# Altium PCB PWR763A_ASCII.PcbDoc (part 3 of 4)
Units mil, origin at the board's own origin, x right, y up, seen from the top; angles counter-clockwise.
Board outline 5000 x 7000 mil, 4 copper layers (Top Layer, Signal Layer 1, Signal Layer 2, Bottom Layer), stack 61.2 mil thick; 559 components, 281 nets, 1477 pads, 685 vias.
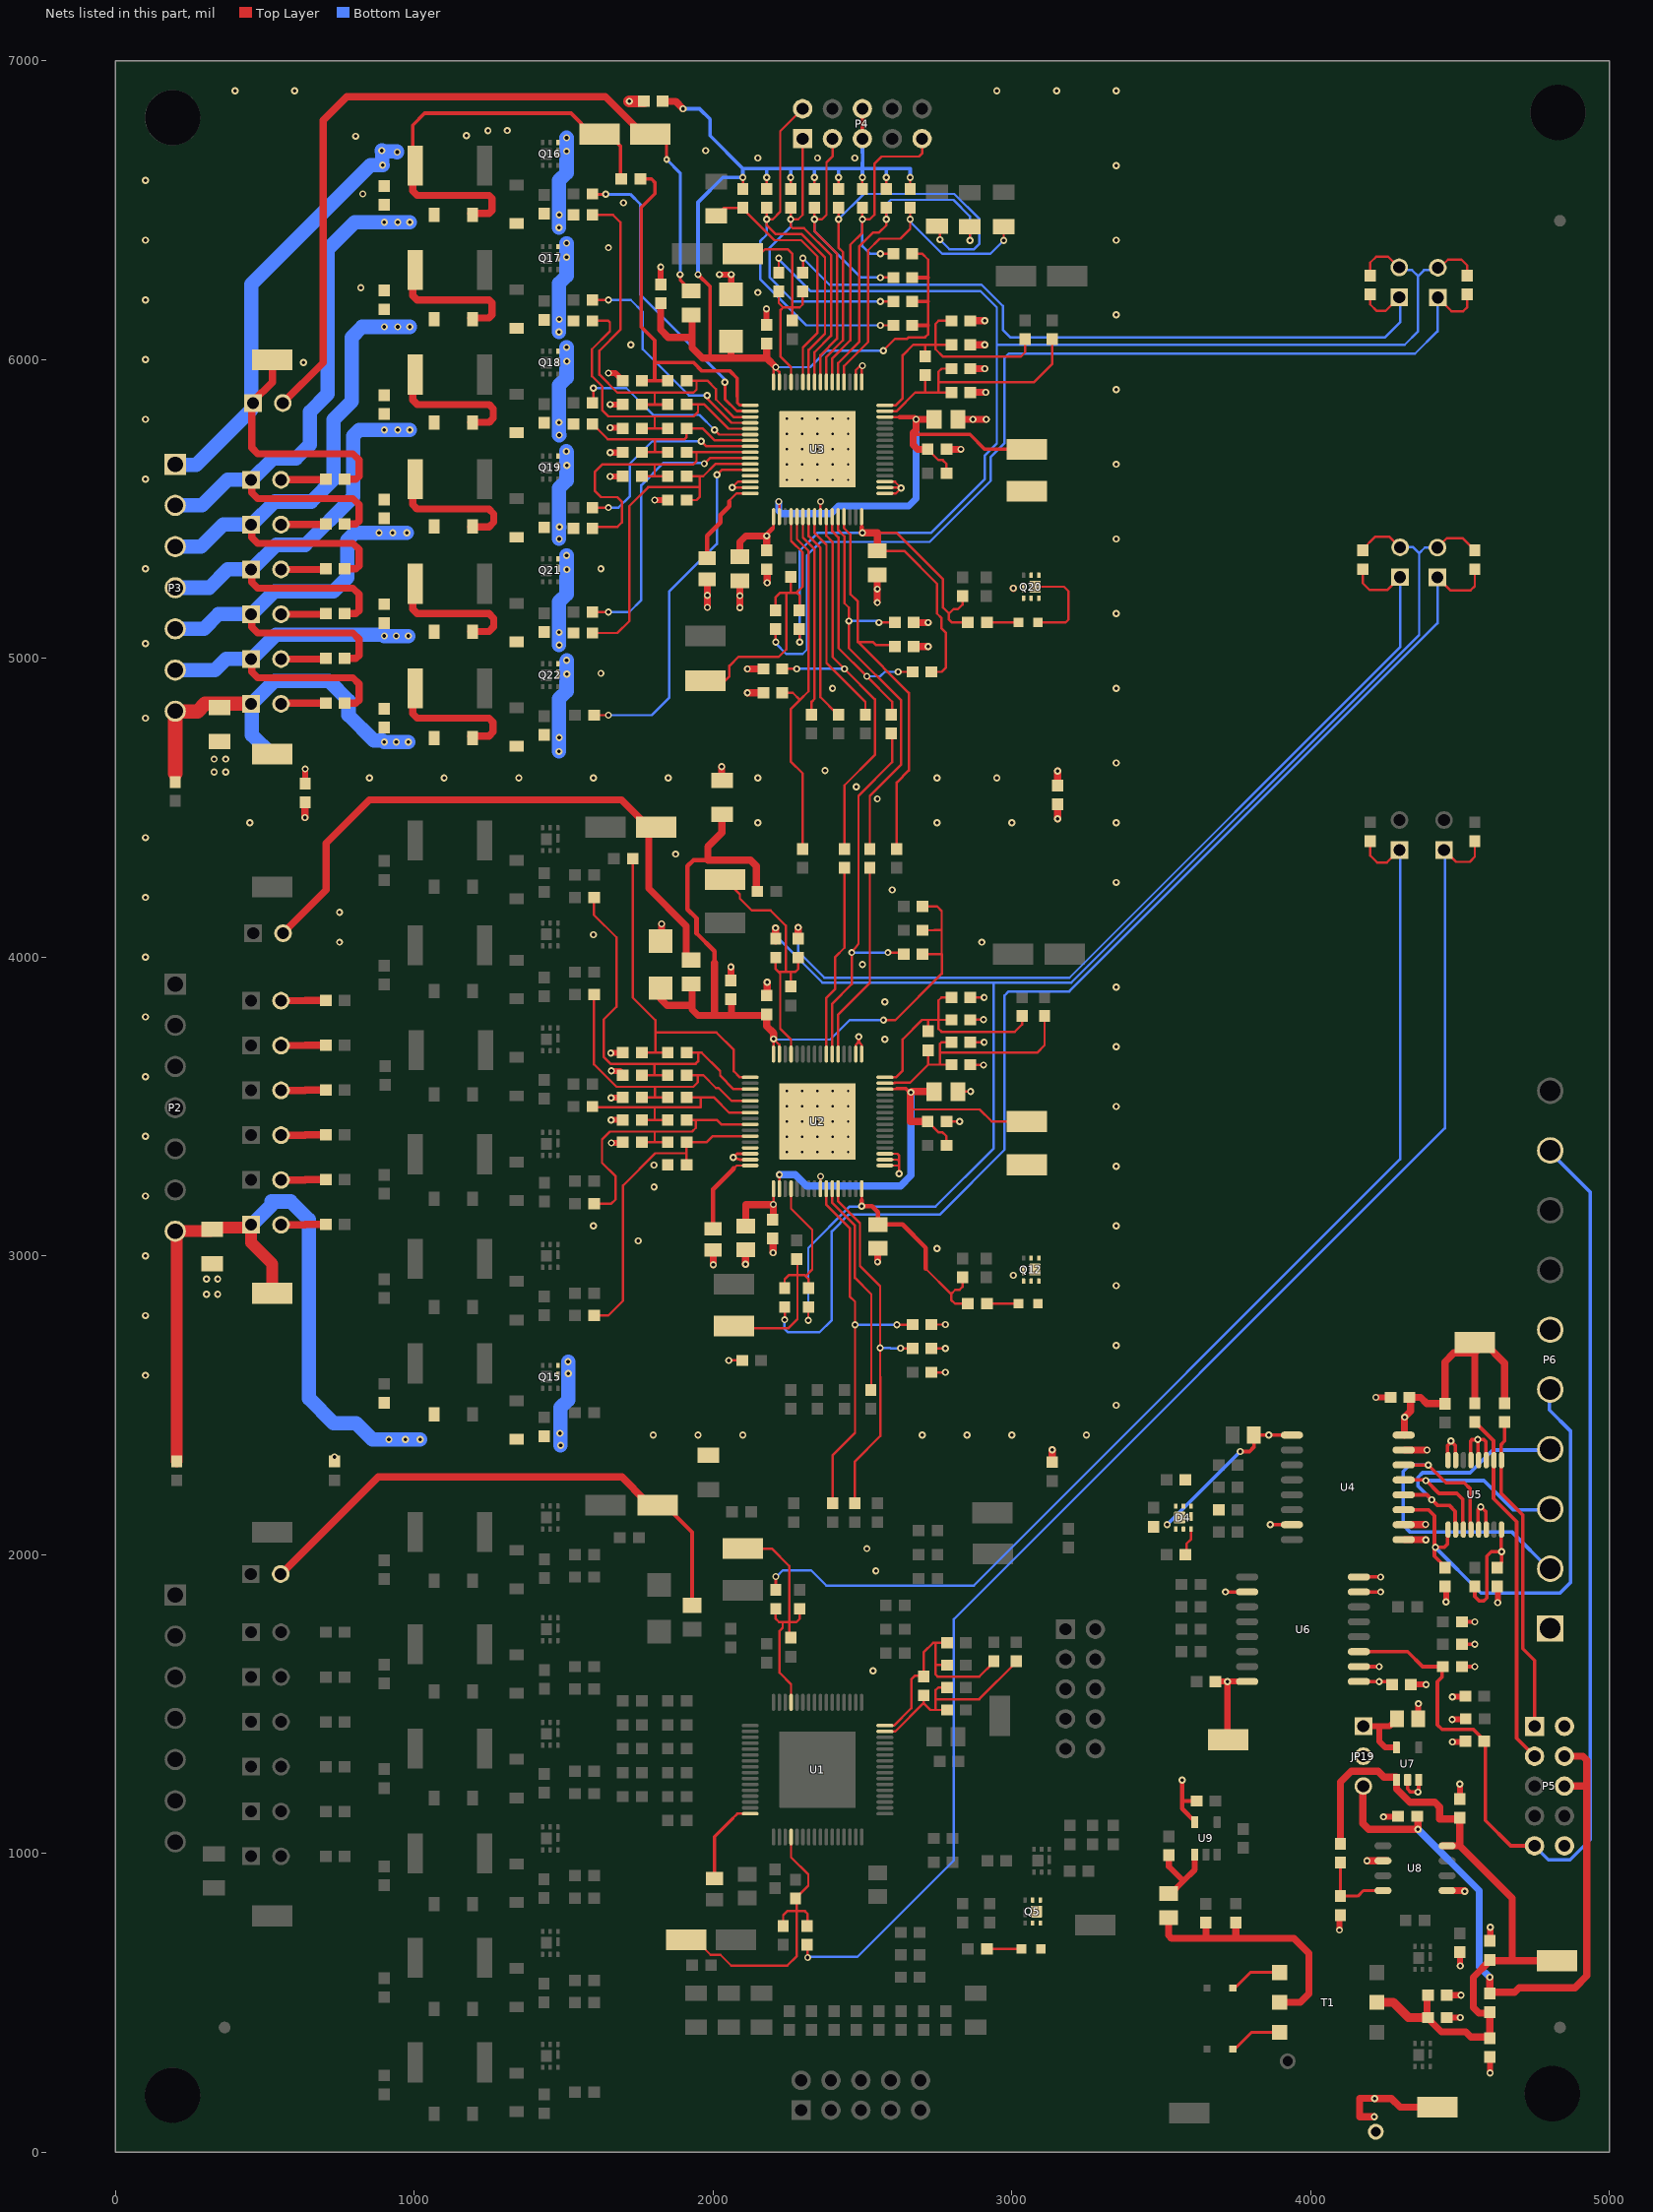
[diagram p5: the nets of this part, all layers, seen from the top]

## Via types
v1: diameter 24, hole 12, Top Layer to Bottom Layer, tented both sides, 607 vias
v2: diameter 19.68, hole 7.87, Top Layer to Bottom Layer, 75 vias
v3: diameter 22, hole 10, Top Layer to Bottom Layer, tented both sides, 3 vias

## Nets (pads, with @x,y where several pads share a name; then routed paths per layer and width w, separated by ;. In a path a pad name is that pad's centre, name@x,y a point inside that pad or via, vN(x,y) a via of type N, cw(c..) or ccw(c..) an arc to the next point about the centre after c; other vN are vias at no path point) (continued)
2-LDOA: C82.1 C83.1 U2.17 | length 266.4
  Top Layer w8: v1@2201,3171 v1(2202,3172) 2202.36,3172.36 U2.17@2202.36,3224.61
  Top Layer w24: C83.1@2110,3100 2110,3171 v1@2201,3171 ; v1(2202,3172) 2202,3127 2200,3125 C82.1@2202.41,3125
2-LDOD1: C84.1 C85.1 R135.2 TP-VPROG2.1 U2.18 U2.46 | length 1633
  Top Layer w8: U2.18@2222.05,3221.65 v1@2222.05,3263.05 ; U2.46@2578.35,3558.27 2613.27,3558.27 2615,3560 ; 2660,3490 2892.96,3490 2932.96,3450 TP-VPROG2.1@3050,3450 ; v1@2660,3545 2662.55,3547.55 v1(2662.79,3547.55) ; C84.1@2718.5,3448.94 C84.1@2718.5,3450 2754.43,3414.07 2767.6,3414.07 2781.5,3400.17 R135.2@2781.5,3370
  Top Layer w12: 2615,3560 2645,3560 v1@2660,3545
  Top Layer w24: v1@2660,3545 2660,3490 2660,3450 C84.1@2715,3450 ; v1@2662.55,3547.55 2665,3550 C85.1@2740,3550
  Bottom Layer w24: v1(2222,3272) 2275.22,3272 2313.06,3234.16 2627.69,3234.16 2662.79,3269.26 v1(2662.79,3547.55)
2-REG50: C58.1 C59.1 C81.1 J5.2 J6.2 R123.2 R126.2 RT3.2 RT4.2 U2.32 | length 5811
  Top Layer w8: v1(2319.03,2784.19) C58.1@2319.03,2827.53 ; 2497.64,3186.36 U2.32@2497.64,3224.61 ; 2712,2957 2797,2872 ; R126.2@2835,2928.5 2835,2896 2825,2886 2811,2886 2797,2872 ; R123.2@2853.5,2840 2810,2840 2797,2853 2797,2872 ; RT4.2@4175,5361.5 4175,5366 4216,5407 4265,5407 J6.2@4300,5372 ; J5.2@4425,5371 4457,5403 4508.5,5403 RT3.2@4550,5361.5
  Top Layer w15: 2497.64,3186.36 2497.64,3166.36 2532.64,3166.36 2552,3147 C81.1@2552,3105 2634,3105 2712,3027 2712,2957
  Top Layer w24: C59.1@2208.97,4054.47 v1(2208.97,4097.81)
  Bottom Layer w8: v1@2209.82,4102.12 2209.82,4071.41 2366.13,3915.09 2938.76,3915.09 ; v1(2319.03,2784.19) 2319.03,3026.1 2457.93,3165 2745,3165 2938.76,3358.76 2938.76,3915.09 ; J6.2@4300,5372 4343.63,5372 4363.7,5351.93 ; J5.2@4425,5371 4382.77,5371 4363.7,5351.93 ; 2938.76,3915.09 3199.83,3915.09 4363.7,5078.97 4363.7,5351.93
  other v1: 2498,3166
2-SCLK_N: R26.1 U2.55 | length 641.7
  Top Layer w8: U2.55@2379.53,3678.35 2379.53,3863.98 2409.05,3893.5 2409.05,4000.58 2440,4031.53 R26.1@2440,4295
2-SCLK_S: C73.1 R43.2 U2.26 | length 1307.6
  Top Layer w8: U2.26@2379.53,3221.65 2379.53,3171.02 2457.54,3093.01 2457.54,2864.39 2475.48,2846.46 v1(2475.48,2769.55) 2475.48,2407.24 2400,2331.77 R43.2@2400,2175 ; v1(2615.39,2769.55) 2665,2769.55 C73.1@2665,2770
  Bottom Layer w8: v1(2475.48,2769.55) v1(2615.39,2769.55)
2-SDI_N: R27.1 U2.53 | length 660.6
  Top Layer w8: U2.53@2418.9,3678.35 2418.9,3807.9 2525,3914 R27.1@2525,4295
2-SDI_S: C74.1 R44.2 U2.28 | length 1246.9
  Top Layer w8: U2.28@2418.9,3221.65 2418.9,3181.98 2491.93,3108.95 2491.93,2965.98 2559.43,2898.49 v1(2559.43,2691.49) 2559.43,2596.03 2560,2595.46 2560,2396.77 2475,2311.77 R44.2@2475,2175 ; v1(2627.91,2690.76) 2665,2690.76 C74.1@2665,2690
  Bottom Layer w8: v1(2559.43,2691.49) 2593.3,2691.49 2594.04,2690.76 v1(2627.91,2690.76)
2-SDO_N: C65.2 R23.1 U2.54 | length 1324.5
  Top Layer w8: U2.54@2399.21,3678.35 2399.21,3844.21 2464.24,3909.24 v1(2464.24,4015.4) 2487.02,4044.19 2487.02,4540 2600,4652.98 R23.1@2600,4745 ; v1(2585.65,4015.4) 2635,4015.4 C65.2@2635,4010
  Bottom Layer w8: v1(2464.24,4015.4) v1(2585.65,4015.4)
2-SDO_S: R41.2 U2.27 | length 720.8
  Top Layer w8: U2.27@2399.21,3221.65 2399.21,3177.25 2475.09,3101.37 2475.09,2926.39 2530,2871.47 R41.2@2530,2555
2-VBAT: C50.1 C62.1 C63.1 C64.1 C65.1 C79.1 R29.1 R115.2 U2.63 U2.64 Z15.2 | length 2850.2
  Top Layer w8: U2.64@2202.36,3678.35 2202.36,3715.49 2207.93,3721.06 v1(2203,3726) 2222.05,3706.95 U2.63@2222.05,3678.35 ; v1(2570.77,3789.14) 2610.4,3789.14 2765.65,3944.39 2765.65,4009.95 2765.45,4010.14 ; C65.1@2705,4010 2740.66,4010 2740.8,4010.14 2765.45,4010.14 ; C64.1@2705,4090 2740.32,4090 2741.13,4090.81 2765.45,4090.81 ; C63.1@2705,4170 2750.09,4170 2765.45,4154.64 2765.45,4090.81 ; 2765.45,4010.14 2765.45,4090.81
  Top Layer w15: 1982.5,4325 1935,4325 1915,4305 1915,4160 1945,4130 1945,4080 2005,4020 2005,3980
  Top Layer w24: Z15.2@1825,3905.5 1825,3859.29 1846,3838.29 1930,3838.29 ; R115.2@1930,3915 1930,3838.29 ; 2005,3980 2005,3805 ; R29.1@2030,4477.91 2030,4417 1982.5,4369.5 1982.5,4325 2125,4325 2145,4305 C62.1@2145,4220 ; C50.1@2060,3855 2061.83,3855 2061.83,3805 ; v1(2203,3726) 2203,3745.86 2180,3768.86 2180,3805 2061.83,3805 ; 1930,3838.29 1930,3824.76 1949.76,3805 2005,3805 ; 2005,3805 2061.83,3805
  Bottom Layer w8: v1(2203,3726) 2210.96,3724.09 2392.31,3724.09 2457.36,3789.14 v1(2570.77,3789.14)
2-VC0: C6.1 C7.2 C8.2 C9.1 C48.2 C50.2 C52.2 C55.2 C60.2 C67.2 C70.2 C71.2 C73.2 C74.2 C75.2 C76.2 C77.2 C78.2 C79.2 C80.2 C81.2 C82.2 C83.2 C84.2 C85.2 JP12.1 P2.7 Q12.4 Q12.7 Q15.4 Q15.7 R36.1 R36.2 R37.2 R46.2 R141.2 R146.2 R149.1 TP4.1 TPTP-VSS1.1 U2.13 U2.14 U2.15 U2.25 U2.33 U2.34 U2.35 U2.49 U2.50 U2.65 Z15.1 Z25.2 Z26.2 | length 4407.5
  Top Layer w8: v1(2052.52,2650) C76.2@2095,2650 ; U2.25@2359.84,3221.65 2359.84,3266.16 v1(2359.99,3266.16) ; U2.50@2477.95,3678.35 2477.95,3706.03 2485.57,3713.65 2485.57,3733.65 v1(2487.84,3733.65) 2490.02,3733.65 2490.02,3713.65 2497.64,3706.03 U2.49@2497.64,3678.35 ; U2.33@2578.35,3302.36 2623.27,3302.36 ; U2.34@2578.35,3322.05 2621.16,3322.05 2621.3,3318.29 2623.27,3318.29 ; U2.35@2578.35,3341.73 2616.79,3341.73 2623.27,3335.26 2623.27,3318.29 ; v1(2623.27,3274.99) 2623.27,3302.36 ; C75.2@2735,2610 v1(2777.48,2610) ; C74.2@2735,2690 v1(2777.48,2690) ; C73.2@2735,2770 v1(2777.48,2770) ; C84.2@2783,3450 2783,3449.69 v1(2825.48,3449.69) ; C85.2@2820,3550 v1(2862.48,3550) ; C70.2@2863,3639 2863,3638.69 v1(2905.48,3638.69) ; C71.2@2863,3791 2863,3790.69 v1(2905.48,3790.69) ; R146.2@2865,3715 v1(2907.48,3715) ; R141.2@2865,3865 2865,3864.69 v1(2907.48,3864.69) ; 2623.27,3302.36 2623.27,3318.29
  Top Layer w10: U2.15@2121.65,3322.05 2089.79,3322.05 v1(2067.46,3329.38) 2079.83,3341.73 U2.14@2121.65,3341.73
  Top Layer w20: v1(1658,3679) C48.2@1700.5,3679 ; v1(1659,3455) C60.2@1701.5,3455 ; v1(1659,3529) C55.2@1701.5,3529 ; v1(1660,3378) C67.2@1702.5,3378 ; v1(1660,3619) 1689.5,3619 C52.2@1701.5,3607
  Top Layer w24: v1(634,4467) 634,4517.5 C6.1@635,4518.5 ; Z15.1@1828,4076 v1(1828.03,4111.43) ; v1(2000.97,2970.57) 2000.97,3019 C77.2@2002,3019 ; C50.2@2060,3932 v1(2060.03,3967.43) ; v1(2108.97,2971.57) 2108.97,3020 C83.2@2110,3020 ; C79.2@2180,3868 2181.03,3868 v1(2181.03,3916.43) ; v1(2200.97,3010.57) 2200.97,3059 C82.2@2202,3059 ; v1(2550.97,2979.57) C81.2@2551,3015 ; C9.1@3135.04,2313 v1(3135.04,2350.89) ; v1(3154,4463) C7.2@3154,4508
  Top Layer w40: P2.7@200,3073.23 209.77,3083 317.74,3083 R36.2@323.01,3088.27 329.74,3095 445,3095 JP12.1@454,3104 454,3044 525,2973 TP4.1@525,2875 ; R37.2@205,2311.5 P2.7@205,3068.23
  Bottom Layer w48: JP12.1@456,3104 522,3170 ; 522,3182 586,3182 647,3121 647,2523 730,2440 805,2440 860,2385 v1(915,2385) v1(970,2385) v1(1020,2385) ; v1(1490,2366) 1490,2493 1515,2518 v1(1515,2646)
  other v1: 2536,1611 2545,1945 2515,2020 733,2327 1800,2400 1950,2400 2100,2400 2700,2400 2850,2400 3000,2400 3250,2400 1488,2406 3350,2500 100,2600 1516,2606 3350,2700 100,2800 305,2871.31 342,2871.31 3350,2900 305,2922.31 342,2922.31 3005,2935 100,3000 2750,3025 1750,3050 1600,3100 3350,3100 100,3200 1803,3231 3350,3300 1802,3304 100,3400 3350,3500 100,3600 3350,3700 100,3800 3350,3900 100,4000 750,4050 2900,4050 1600,4075 750,4150 100,4200 3350,4250 1875,4345 100,4400 450,4450 2150,4450 2750,4450 3000,4450 3350,4450
  other v2: 2247.64,3347.64 2298.82,3347.64 2350,3347.64 2401.18,3347.64 2452.36,3347.64 2247.64,3398.82 2298.82,3398.82 2350,3398.82 2401.18,3398.82 2452.36,3398.82 2247.64,3450 2298.82,3450 2350,3450 2401.18,3450 2452.36,3450 2247.64,3501.18 2298.82,3501.18 2350,3501.18 2401.18,3501.18 2452.36,3501.18 2247.64,3552.36 2298.82,3552.36 2350,3552.36 2401.18,3552.36 2452.36,3552.36
2-VC1: C68.2 C78.1 R145.1 U2.11 | length 1056.2
  Top Layer w8: R145.1@1601.5,2800 1649.25,2800 1698.45,2849.2 1698.45,3234.88 1806.95,3343.38 1909.99,3343.38 ; C78.1@1911.5,3305 C68.2@1911.5,3380 1978,3380 1998.79,3400.79 U2.11@2124.61,3400.79
2-VC2: C61.2 C67.1 C68.1 R138.1 U2.9 | length 997.1
  Top Layer w8: R138.1@1601.5,3175 1659.81,3175 1674.37,3189.56 1674.37,3265.59 1628.52,3311.44 1628.52,3389.95 1654.63,3416.06 1805,3416.06 ; C67.1@1761.5,3380 1805,3380 ; C68.1@1848.5,3380 1805,3380 ; C61.2@1911.5,3455 1942.29,3455 ; U2.9@2124.61,3440.16 2027.52,3440.16 2012.68,3455 1942.29,3455 ; 1805,3380 1805,3416.06 ; 1805,3416.06 1930.23,3416.06 1942.29,3428.12 1942.29,3455
2-VC3: C56.2 C60.1 C61.1 R131.1 U2.7 | length 759.7
  Top Layer w8: R131.1@1596.5,3500 1599.43,3497.07 1805,3497.07 ; C60.1@1761.5,3455 1805,3455 ; C61.1@1848.5,3455 1805,3455 ; C56.2@1911.5,3530 1959,3530 ; U2.7@2124.61,3479.53 2054.19,3479.53 2003.72,3530 1959,3530 ; 1805,3455 1805,3497.07 ; 1805,3497.07 1959,3497.07 1959,3530
2-VC4: C53.2 C55.1 C56.1 R122.1 U2.5 | length 1014.9
  Top Layer w8: R122.1@1601.5,3875 1601.5,3641.5 1677,3566 1805.82,3566 ; C55.1@1761.5,3530 1807,3530 ; C56.1@1848.5,3530 1807,3530 ; C53.2@1911.5,3605 1949,3605 ; U2.5@2124.61,3518.9 2062.2,3518.9 2019.1,3562 2010.07,3562 1967.07,3605 1949,3605 ; 1805.82,3566 1934.26,3566 1949,3580.74 1949,3605 ; 1805.82,3566 1805.82,3531.19 1807,3530
2-VC5: C49.2 C52.1 C53.1 R118.1 U2.3 | length 1338.8
  Top Layer w8: R118.1@1601.5,4200 1601.5,4141.5 1677,4066 1677,3834.04 1634,3791.04 1634,3666 1656.79,3643.21 1804,3643.21 ; C52.1@1761.5,3605 1803,3605 ; C53.1@1848.5,3605 1803,3605 ; C49.2@1911.5,3680 1950.22,3680 ; U2.3@2124.61,3558.27 2068.91,3558.27 2023.94,3603.24 2023.94,3618.28 1962.22,3680 1950.22,3680 ; 1803,3605 1804,3606 1804,3643.21 ; 1804,3643.21 1942.17,3643.21 1950.22,3651.26 1950.22,3680
2-VC6: C48.1 C49.1 R114.1 U2.1 | length 1190.1
  Top Layer w8: R114.1@1731.5,4330 1731.5,3864.5 1807,3789 1807,3746.91 ; C48.1@1761.5,3680 1807,3680 ; C49.1@1848.5,3680 1807,3680 ; U2.1@2124.61,3597.64 2090.36,3597.64 2070,3618 2070,3689 2011.1,3747.9 1807.99,3747.9 1807,3746.91 ; 1807,3680 1807,3746.91
3-ALERT_N: C2.2 P4.1 R4.1 U3.57 | length 1646
  Top Layer w8: R4.1@2260,6505 v1(2260,6470) ; P4.1@2300,6740 2300,6485 2285,6470 v1(2260,6470) ; U3.57@2340.16,5928.35 2340.16,5969.84 2340,5970 2340,6025 2395,6080 2395,6350 2305,6440 2267,6440 2260,6447 v1(2260,6470) ; v1(2560,6195) C2.2@2600,6195
  Bottom Layer w8: v1(2260,6470) 2260,6445 2190,6375 2190,6275 2270,6195 v1(2560,6195)
3-ALERT_S: R21.2 U3.23 | length 700.8
  Top Layer w8: U3.23@2320.47,5471.65 2320.47,5409.53 2360,5370 2360,4870 2415,4815 R21.2@2420,4815
3-CB1: R186.1 U3.12 | length 1207.1
  Top Layer w8: R186.1@1601.5,4810 v1(1650,4810) ; v1(2013,5615) 2029.1,5631.1 U3.12@2124.61,5631.1
  Bottom Layer w8: v1(1650,4810) 1795,4810 1853,4868 1853,5223 2013,5383 v1(2013,5615)
3-CB2: R178.1 U3.10 | length 967.4
  Top Layer w8: R178.1@1596.5,5155 v1(1650,5155) ; v1(1971,5652) 1989.47,5670.47 U3.10@2124.61,5670.47
  Bottom Layer w8: v1(1650,5155) 1720,5155 1760,5195 1760,5580 1835,5655 v1@1970,5655
3-CB3: R173.1 U3.8 | length 691
  Top Layer w8: R173.1@1596.5,5505 v1(1650,5505) ; v1(1961,5727) 1978.16,5709.84 U3.8@2124.61,5709.84
  Bottom Layer w8: v1(1650,5505) 1684,5505 1721,5542 1721,5651 1797,5727 v1(1961,5727)
3-CB4: R162.1 U3.6 | length 640.6
  Top Layer w8: R162.1@1596.5,5855 1600,5858.5 v1(1600,5905) ; v1(2005,5765) 2020.79,5749.21 U3.6@2124.61,5749.21
  Bottom Layer w8: v1(1600,5905) 1710,5905 1800,5815 1955,5815 v1(2005,5765)
3-CB5: R157.1 U3.4 | length 770.6
  Top Layer w8: R157.1@1600,6200 v1(1650,6200) ; v1(1980,5880) 1980,5871 2062.42,5788.58 U3.4@2121.65,5788.58
  Bottom Layer w8: v1(1650,6200) 1725,6200 1765,6160 1765,6035 1920,5880 v1(1980,5880)
3-CB6: R153.1 U3.2 | length 1045.4
  Top Layer w10: R153.1@1596.5,6555 1597.5,6554 v1(1641,6554) ; v1(2040,5925) 2040,5868 2080.05,5827.95 U3.2@2124.61,5827.95
  Bottom Layer w10: v1(1641,6554) 1723,6554 1757,6520 1757,6217 2040,5934 v1(2040,5925)
3-CELL1: C103.2 C113.1 JP5.1 P3.6 Q21.4 Q21.7 R18.2 R180.1 R182.2 R183.2 Z36.2 Z37.2 Z38.1 | length 2142.3
  Top Layer w24: JP5.1@456,4998 456,4955 476,4935 795,4935 815,4915 815,4860 805,4850 R18.2@770,4850 ; R183.2@995,4900 995,4815 1010,4800 1250,4800 1263.94,4786.06 1263.94,4753.94 1250,4740 Z38.1@1189.5,4740
  Bottom Layer w48: P3.6@200,4961.02 333.02,4961.02 370,4998 456,4998 537,5079 896,5079 v1(900,5075) v1(940,5075) v1(980,5075) ; v1(1485,5045) 1485,5085 v1(1484.88,5087.01) 1485,5087.01 1485,5190 1510,5215 1510,5297.49 v1(1510.31,5297.49) 1510,5305 v1(1510,5345)
3-CELL2: C100.2 C103.1 JP4.1 P3.5 Q19.4 Q19.7 R17.2 R174.1 R175.2 R176.2 Z34.2 Z35.2 Z36.1 | length 2292.6
  Top Layer w8: v1(1509.17,5693.1) 1509.57,5691.11 1509.77,5691.15 v1@1510,5690
  Top Layer w24: JP4.1@456,5148 456,5105 476,5085 795,5085 815,5065 815,5010 805,5000 R17.2@770,5000 ; R176.2@995,5250 995,5165 1010,5150 1250,5150 1265.73,5134.27 1265.73,5105.73 1250,5090 Z36.1@1189.5,5090
  Bottom Layer w48: P3.5@200,5098.81 295.82,5098.82 345,5148 456,5148 532,5224 730,5224 776,5270 776,5395 801,5420 v1(882,5420) v1(928,5420) v1(975,5420) ; v1(1485,5400) 1485,5435 v1(1486,5440) 1485,5440 1485,5570 1510,5595 1510,5646.51 v1(1510.58,5646.51) 1510,5651 1510,5690 1509.77,5691.15 1509.57,5691.11 v1(1509.17,5693.1)
3-CELL3: C95.2 C100.1 JP3.1 P3.4 Q18.4 Q18.7 R16.2 R163.1 R164.2 R167.2 Z32.2 Z33.2 Z34.1 | length 2432.5
  Top Layer w24: JP3.1@456,5298 456,5255 476,5235 795,5235 815,5215 815,5160 805,5150 R16.2@770,5150 ; R167.2@995,5600 995,5515 1010,5500 1250,5500 1266.09,5483.91 1266.09,5456.09 1250,5440 Z34.1@1189.5,5440
  Bottom Layer w48: P3.4@200,5236.61 313.61,5236.61 375,5298 456,5298 538,5380 635,5380 795,5540 795,5745 815,5765 v1(900,5765) v1(945,5765) v1(985,5765) ; v1(1485.17,5747.45) 1485,5750 1485,5785 v1(1484,5790) 1485,5790 1485,5915 1510,5940 1510,5994.7 v1(1510.65,5994.7) 1510,6000 1510,6040 v1(1509.91,6041.1)
3-CELL4: C92.2 C95.1 JP2.1 P3.3 Q17.4 Q17.7 R15.2 R158.1 R159.2 R160.2 Z30.2 Z31.2 Z32.1 | length 2642.7
  Top Layer w24: JP2.1@456,5448 456,5405 476,5385 795,5385 815,5365 815,5310 805,5300 R15.2@770,5300 ; R160.2@995,5950 995,5865 1010,5850 1250,5850 1264.66,5835.34 1264.66,5804.66 1250,5790 Z32.1@1189.5,5790
  Bottom Layer w48: P3.3@200,5374.41 286.41,5374.41 360,5448 456,5448 533,5525 655,5525 730,5600 730,5800 790,5860 790,6075 825,6110 v1(900,6110) v1(945,6110) v1(985,6110) ; v1(1484.47,6092.3) 1485,6095 v1(1485,6135) 1485,6255 1510,6280 1510,6342.93 v1(1509.8,6342.93) 1510,6350 v1(1510,6390)
3-CELL5: C89.2 C92.1 JP1.1 P3.2 Q16.4 Q16.7 R14.2 R154.1 R155.2 R156.2 Z28.2 Z29.2 Z30.1 | length 2835.3
  Top Layer w24: JP1.1@456,5598 456,5555 476,5535 795,5535 815,5515 815,5460 805,5450 R14.2@770,5450 ; R156.2@995,6300 995,6215 1010,6200 1250,6200 1260,6190 1260,6150 1250,6140 Z30.1@1189.5,6140
  Bottom Layer w48: P3.2@200,5512.2 200.8,5513 290,5513 375,5598 456,5598 528,5670 605,5670 650,5715 650,5825 710,5885 710,6370 800,6460 v1(900,6460) v1(945,6460) v1(985,6460) ; v1(1484.6,6441.83) 1485,6445 v1(1485,6485) 1485,6600 1510,6625 1510,6697.97 v1(1509.87,6697.97) 1510,6700 1510,6740 v1(1510.04,6742.79)
3-CELL6: C89.1 J7.1 P3.1 R13.2 R150.2 R151.2 TP1.1 TP-C5.1 Z28.1 | length 3734.5
  Top Layer w12: R150.2@995,6650 995,6785 1035,6825 1525,6825 1595,6755 1650,6755 1690,6715 R151.2@1690,6608.5
  Top Layer w24: J7.1@455,5850 456,5850 456,5705 476,5685 795,5685 815,5665 815,5610 805,5600 R13.2@770,5600 ; J7.1@460,5855 460,5860 525,5925 TP1.1@525,6000 ; R150.2@995,6650 995,6565 1010,6550 1250,6550 1260,6540 1260,6500 1250,6490 Z28.1@1189.5,6490
  Bottom Layer w48: P3.1@200,5650 202,5648 270,5648 455,5833 455,6252 854,6651 v1@892.5,6651 ; v1(894,6651) v1@892.5,6651 ; v1(943,6695) 943,6697.5 v1@892.5,6697.5 ; v1@892.5,6651 v1@892.5,6697.5 ; v1@892.5,6697.5 891,6697.5 v1(891,6700) 892.5,6700 v1@892.5,6697.5
3-CONV_N: R1.1 R2.1 U3.59 | length 853.3
  Top Layer w8: R1.1@2011,6481.91 2037.59,6508.5 R2.1@2100,6508.5 ; R2.1@2100,6505 2205,6400 2295,6400 2350,6345 2350,6090 2300.79,6040.79 U3.59@2300.79,5928.35
3-CONV_S: C111.1 R25.2 U3.21 | length 1233.6
  Top Layer w8: C111.1@2231.5,4885 2267,4885 2291,4861 ; U3.21@2281.1,5471.65 2281.1,5398.9 2320,5360 2320,4890 2291,4861 ; R25.2@2300,4365 2300,4615.17 2260,4655.17 2260,4830 2291,4861
3-CS_N: R9.1 R12.1 U3.52 | length 1146.9
  Top Layer w8: U3.52@2438.58,5928.35 2438.58,5978.58 2519,6059 2519,6366 2558,6405 2627,6405 2660,6438 v1(2660,6470) R9.1@2660,6505 ; R12.1@2958.87,6446.72 2973.24,6432.35 v1(2973.24,6399.38)
  Bottom Layer w8: v1(2660,6470) 2660,6462 2768,6354 2927.86,6354 v1(2973.24,6399.38)
3-CS_S: C110.1 R28.2 U3.29 | length 1339.5
  Top Layer w8: U3.29@2438.58,5471.65 2438.58,5436.42 2460,5415 2460,5215 2485,5190 2485,5055 ; C110.1@2605,5040 2600,5045 2545,5045 2535,5055 2485,5055 ; R28.2@2615,4365 2615,4584.43 2655.57,4625 2655.57,4884.43 2485,5055
3-DRDY_N: C1.2 P4.2 R3.1 U3.58 | length 1877.6
  Top Layer w8: R3.1@2180,6505 v1(2180,6470) ; P4.2@2300,6840 2225,6765 2225,6495 2200,6470 v1(2180,6470) ; U3.58@2320.47,5928.35 2320.47,6032.97 2375,6087.5 2375,6342.63 2297.63,6420 2210,6420 2180,6450 v1(2180,6470) ; v1(2560,6115) C1.2@2600,6115
  Bottom Layer w8: v1(2180,6470) 2180,6418.81 2159,6397.81 2159,6268.37 2312.37,6115 v1(2560,6115)
3-DRDY_S: R24.2 U3.22 | length 677
  Top Layer w8: U3.22@2300.79,5471.65 2300.79,5404.21 2340,5365 2340,4865 2330,4855 R24.2@2330,4815
3-FAULT_N: C3.2 P4.3 R5.1 U3.56 | length 1304.3
  Top Layer w8: R5.1@2340,6505 v1(2340,6470) ; U3.56@2359.84,5928.35 2359.84,6014.84 2415,6070 2415,6355 2340,6430 v1(2340,6470) ; P4.3@2400,6740 2400,6680 2380,6660 2380,6485 2365,6470 v1(2340,6470) ; v1(2560,6275) C3.2@2600,6275
  Bottom Layer w8: v1(2340,6470) 2340,6430 2495,6275 v1(2560,6275)
3-FAULT_S: R22.2 U3.24 | length 727
  Top Layer w8: U3.24@2340.16,5471.65 2340.16,5419.84 2380,5380 2380,4985 2510,4855 R22.2@2510,4815
3-LDOA: C116.1 C117.1 U3.17 | length 260.9
  Top Layer w8: 2202.36,5437.36 U3.17@2202.36,5471.65
  Top Layer w15: v1(2180,5410) 2180,5415 2200,5435
  Top Layer w24: C117.1@2090,5340 2090,5390 2110,5410 v1(2180,5410) C116.1@2180,5365
3-LDOD1: C118.1 C119.1 R172.2 TP-VPROG3.1 U3.18 U3.46 | length 1655.8
  Top Layer w8: v1(2220,5525) 2222.05,5522.95 U3.18@2222.05,5471.65 ; U3.46@2578.35,5808.27 2625,5808.27 ; C118.1@2718.5,5700 2754.85,5663.65 2768.96,5663.65 2781.5,5651.11 R172.2@2781.5,5620
  Top Layer w12: 2670,5750 2860,5750 2910,5700 TP-VPROG3.1@3050,5700
  Top Layer w15: 2625,5808.27 2675,5808.27 v1(2680,5800)
  Top Layer w24: C118.1@2715,5700 2685,5700 2670,5715 2670,5750 2670,5755 2680,5765 v1(2680,5800) C119.1@2740,5800
  Bottom Layer w24: v1(2220,5525) 2220,5495 2230,5485 2395,5485 2420,5510 2655,5510 2680,5535 v1(2680,5800)
3-REG50: C96.1 C97.1 C115.1 J8.2 J9.2 R161.2 R168.2 R177.1 RT5.2 RT6.2 U3.32 | length 5938.3
  Top Layer w8: C97.1@2220,6291.5 v1(2220,6340) ; v1(2290,5055) C96.1@2290,5095 ; 2497.64,5440 U3.32@2497.64,5471.65 ; C115.1@2550,5360 2640,5360 2750,5250 2750,5150 2765,5135 2765,5100 2780,5085 2780,4970 2765,4955 R177.1@2735,4955 ; 2550,5420 2615,5420 2770,5265 2770,5170 2790,5150 ; R168.2@2835,5205 2835,5180 2820,5165 2805,5165 2790,5150 ; R161.2@2850,5120 2800,5120 2790,5130 2790,5150 ; RT6.2@4200,6270 4200,6325 4220,6345 4260,6345 4300,6305 J9.2@4300,6300 ; J8.2@4425,6300 4460,6335 4505,6335 4525,6315 RT5.2@4525,6270
  Top Layer w15: 2497.64,5440 2497.64,5422.36 v1(2500,5420)
  Top Layer w25: v1(2500,5420) 2550,5420 C115.1@2550,5360
  Bottom Layer w8: v1(2220,6340) 2220,6336 2326,6230 2895,6230 2950,6175 2950,6050 ; v1(2290,5055) 2290,5360 2350,5420 2728.94,5420 2910,5601.06 2910,5680 2950,5720 2950,6050 ; J9.2@4300,6300 4340,6300 4360,6280 ; J8.2@4425,6300 4380,6300 4360,6280 ; 2950,6050 4315,6050 4360,6095 4360,6280
3-SCLK_N: R6.1 R10.1 U3.55 | length 1435.9
  Top Layer w8: U3.55@2379.53,5925.39 2379.53,6009.53 2435,6065 2435,6360 2420,6375 v1(2420,6470) R6.1@2420,6505 ; R10.1@2750,6446.91 2760,6436.91 v1(2760,6402)
  Bottom Layer w8: v1(2420,6470) 2505,6555 2807.63,6555 2892,6470.63 2892,6388 2874,6370 2791,6370 2760,6401 v1(2760,6402)
3-SCLK_S: C108.1 R26.2 U3.26 | length 1421.2
  Top Layer w8: C108.1@2235,4965 v1(2280,4965) ; U3.26@2379.53,5471.65 2379.53,5410.47 2400,5390 2400,5005 v1(2440,4965) 2542,4863 2542,4677 2440,4575 R26.2@2440,4365
  Bottom Layer w8: v1(2280,4965) v1(2440,4965)
3-SDI_N: R8.1 R11.1 U3.53 | length 1141.6
  Top Layer w8: U3.53@2418.9,5928.35 2418.9,5988.9 2490,6060 2490,6380 2535,6425 2555,6425 2580,6450 v1(2580,6470) R8.1@2580,6505 ; v1(2860,6399) R11.1@2860,6445.54
  Bottom Layer w8: v1(2580,6470) 2580,6520 2595,6535 2805,6535 2860,6480 v1(2860,6399)
3-SDI_S: C109.1 R27.2 U3.28 | length 1389.7
  Top Layer w8: U3.28@2418.9,5471.65 2418.9,5429.36 2440,5408.26 2440,5185 2455,5170 v1(2455,5125) 2455,5033.94 2630,4858.94 2630,4645 2525,4540 R27.2@2525,4365 ; v1(2555,5120) C109.1@2605,5120
  Bottom Layer w8: v1(2455,5125) 2550,5125 v1(2555,5120)
3-SDO_N: C5.2 P4.9 R7.1 U3.54 | length 1259.5
  Top Layer w8: U3.54@2399.21,5928.35 2399.21,6004.21 2460,6065 2460,6385 2500,6425 v1(2500,6470) ; R7.1@2500,6505 v1(2500,6470) ; v1(2560,6355) C5.2@2600,6355 ; P4.9@2700,6740 2700,6690 2690,6680 2565,6680 2540,6655 2540,6485 2525,6470 v1(2500,6470)
  Bottom Layer w8: v1(2500,6470) 2500,6380 2525,6355 v1(2560,6355)
3-SDO_S: R23.2 R177.2 U3.27 | length 896
  Top Layer w8: U3.27@2399.21,5471.65 2399.21,5425.79 2420,5405 2420,5035 v1(2515,4940) 2600,4855 R23.2@2600,4815 ; v1(2620,4955) R177.2@2665,4955
  Bottom Layer w8: v1(2515,4940) 2560,4940 2575,4955 v1(2620,4955)
3-VBAT: C1.1 C2.1 C3.1 C4.1 C5.1 C88.1 C114.1 P4.5 P4.6 R2.2 R3.2 R4.2 R5.2 R6.2 R7.2 R8.2 R9.2 R152.2 U3.63 U3.64 Z27.2 | length 4241.1
  Top Layer w8: R2.2@2100,6575 v1(2100,6610) ; R3.2@2180,6575 v1(2180,6610) ; U3.64@2202.36,5928.35 2202.36,5967.36 v1@2207.91,5972.91 ; v1(2210,5975) v1@2207.91,5972.91 ; U3.63@2222.05,5928.35 2222.05,5958.76 v1@2207.91,5972.91 ; R4.2@2260,6575 v1(2260,6610) ; R5.2@2340,6575 v1(2340,6610) ; R6.2@2420,6575 v1(2420,6610) ; R7.2@2500,6575 v1(2500,6610) ; v1(2570,6030) 2610,6070 2650,6070 2655,6075 2710,6075 2720,6085 2720,6115 2720,6195 2720,6275 2720,6335 2700,6355 C5.1@2670,6355 ; R8.2@2580,6575 v1(2580,6610) ; R9.2@2660,6575 v1(2660,6610)
  Top Layer w12: v1(1950,6285) 1990,6245 1990,6005 ; P4.5@2500,6740 P4.6@2500,6840 ; C1.1@2670,6115 2720,6115 ; C2.1@2670,6195 2720,6195 ; C3.1@2670,6275 2720,6275
  Top Layer w24: C114.1@1825,6185 1825,6100 1850,6075 1930,6075 ; C88.1@1835,6865 1875,6865 v1(1900,6840) ; R152.2@1930,6155 1930,6075 ; Z27.2@2060,6070.5 2060,6005 ; C4.1@2180,6050 2180,6005 ; v1(2210,5975) 2180,6005 ; 1930,6075 1930,6040 1965,6005 1990,6005 2060,6005 ; 2060,6005 2180,6005
  Bottom Layer w8: v1(2210,5975) 2325,5975 2380,6030 v1(2570,6030)
  Bottom Layer w12: v1(1900,6840) 1955,6840 1990,6805 1990,6750 2100,6640 ; v1(1950,6285) 1950,6527.09 2032.91,6610 v1(2100,6610) 2100,6640 ; v1(2180,6610) 2180,6640 ; v1(2260,6610) 2260,6640 ; v1(2340,6610) 2340,6640 ; v1(2420,6610) 2420,6640 ; v1(2500,6610) 2500,6640 ; P4.5@2500,6740 2500,6692.13 2501,6691.13 2501,6660.62 2500,6659.62 2500,6640 ; v1(2580,6610) 2580,6640 ; v1(2660,6610) 2660,6640 2580,6640 ; 2100,6640 2180,6640 ; 2180,6640 2260,6640 ; 2260,6640 2340,6640 ; 2340,6640 2420,6640 ; 2420,6640 2500,6640 ; 2500,6640 2580,6640
3-VC0: C4.2 C6.2 C7.1 C86.2 C88.2 C90.2 C93.2 C98.2 C101.2 C104.2 C105.2 C107.2 C108.2 C109.2 C110.2 C111.2 C112.2 C113.2 C114.2 C115.2 C116.2 C117.2 C118.2 C119.2 JP6.1 P3.7 Q20.4 Q20.7 Q22.4 Q22.7 R19.1 R19.2 R20.2 R29.2 R181.2 R185.2 R187.1 TP2.1 TP-VSS2.1 U3.13 U3.14 U3.15 U3.25 U3.33 U3.34 U3.35 U3.49 U3.50 U3.65 Z27.1 Z38.2 Z39.2 | length 3647.8
  Top Layer w8: v1(2064,5572) v1(2064,5572) ; U3.15@2121.65,5572.05 v1(2064,5572) ; U3.14@2121.65,5591.73 2083.73,5591.73 v1(2064,5572) ; U3.25@2359.84,5471.65 2359.84,5524.84 v1(2360,5525) ; U3.50@2477.95,5928.35 2477.95,5965 2492.95,5980 v1(2500,5980) 2497.64,5977.64 U3.49@2497.64,5928.35 ; U3.33@2578.35,5552.36 2612.36,5552.36 v1(2630,5570) v1@2627.95,5572.05 ; U3.34@2578.35,5572.05 v1@2627.95,5572.05 ; U3.35@2578.35,5591.73 2610,5591.73 2610,5590 v1@2627.95,5572.05
  Top Layer w20: R20.2@200,4590 200,4615 ; C6.2@635,4581.5 v1(635,4630) ; v1(1650,5955) 1673.5,5955 C86.2@1698.5,5930 ; v1(1656,5609) C101.2@1698.5,5609 ; v1(1656,5689) C98.2@1698.5,5689 ; v1(1656,5772) C93.2@1698.5,5772 ; v1(1656,5850) C90.2@1698.5,5850 ; v1(1805,5530) C107.2@1848.5,5530 ; C114.2@1825,6251.5 v1(1825,6310) ; v1(2022,6285) v1(2061,6285) 2061,6219.74 Z27.1@2060,6218.74 ; v1(2179,6170) 2179,6117.5 C4.2@2180,6116.5
  Top Layer w24: v1(1981,5171) v1(1981,5211) C112.2@1981,5261 ; R29.2@2029,4593 v1(2029,4638) ; v1(2090,5170) v1(2090,5210) C117.2@2090,5260 ; v1(2115,4885) C111.2@2165,4885 ; v1(2115,4965) C108.2@2165,4965 ; v1(2181,5253) C116.2@2181,5298 ; v1(2550,5187) v1(2550,5232) C115.2@2550,5277 ; C110.2@2675,5040 v1(2720,5040) ; C109.2@2675,5120 v1(2720,5120) ; C118.2@2785,5700 v1(2830,5700) ; C119.2@2820,5800 v1(2870,5800) v1(2915,5800) ; R185.2@2865,5970 v1(2910,5970) ; R181.2@2865,6050 v1(2910,6050) ; C105.2@2865,6131 v1(2910,6131) ; C104.2@2868,5891 v1(2913,5891) ; v1(3005,5235) v1@3005.91,5234.09 ; C7.1@3154,4578 v1(3154,4623)
  Top Layer w40: v1(1720,6865) C88.2@1768.5,6865
  Top Layer w48: 200,4615 P3.7@200,4823 ; P3.7@200,4823.22 P3.7@200,4823 ; JP6.1@456,4848 350,4848 300,4848 275,4823 P3.7@200,4823
  Bottom Layer w48: 520,4680 456,4744 456,4848 532,4924 715,4924 780,4859 780,4810 865,4725 895,4725 v1(900,4720) v1(940,4720) v1(980,4720) ; v1(1484.22,4688.31) 1485,4695 v1(1485,4735) 1485,4865 1510,4890 1510,4947.07 v1(1510.48,4947.07) 1510,4950 1510,4990 v1(1510.07,4994.07)
  other v1: 2575,3725 2575,3850 2500,3975 2600,4225 2550,4530 2480,4570 850,4600 1100,4600 1350,4600 1600,4600 1850,4600 2150,4600 2750,4600 2950,4600 330,4620 369,4620 2375,4625 3350,4650 330,4663 369,4663 100,4800 2400,4900 3350,4900 1625,4950 100,5050 3350,5150 100,5300 1625,5300 3350,5400 100,5600 3350,5650 100,5800 3350,5900 629,5991 100,6000 1725,6050 3350,6150 100,6200 2150,6225 821,6241 1650,6375 100,6400 3350,6400 1700,6525 828,6555 100,6600 3350,6650 2150,6675 2350,6675 2475,6675 1975,6700 804,6748 1175,6750 1246.62,6766.94 1311.64,6767.13 400,6900 600,6900 2950,6900 3150,6900 3350,6900
  other v2: 2247.64,5597.64 2298.82,5597.64 2350,5597.64 2401.18,5597.64 2452.36,5597.64 2247.64,5648.82 2298.82,5648.82 2350,5648.82 2401.18,5648.82 2452.36,5648.82 2247.64,5700 2298.82,5700 2350,5700 2401.18,5700 2452.36,5700 2247.64,5751.18 2298.82,5751.18 2350,5751.18 2401.18,5751.18 2452.36,5751.18 2247.64,5802.36 2298.82,5802.36 2350,5802.36 2401.18,5802.36 2452.36,5802.36
3-VC1: C102.2 C107.1 R182.1 U3.11 | length 1133.8
  Top Layer w8: R182.1@1596.5,5085 1680,5085 1720,5125 1720,5510 1783,5573 1955,5573 ; C107.1@1911.5,5530 1945,5530 1955,5540 1955,5573 ; C102.2@1911.5,5610 1955,5610 ; U3.11@2124.61,5650.79 2007.79,5650.79 1967,5610 1955,5610 ; 1955,5573 1955,5610
3-VC2: C99.2 C101.1 C102.1 R175.1 U3.9 | length 1046.9
  Top Layer w8: R175.1@1605,5440 1680,5440 1695,5455 1695,5525 1680,5540 1625,5540 1605,5560 1605,5625 1630,5650 1805,5650 ; C101.1@1765,5610 1805,5610 ; C102.1@1845,5610 1805,5610 ; C99.2@1915.16,5690.16 1945,5690.16 ; U3.9@2121.65,5690.16 1945,5690.16 ; 1805,5610 1805,5650 ; 1805,5650 1935,5650 1945,5660 1945,5690.16
3-VC3: C94.2 C98.1 C99.1 R164.1 U3.7 | length 729.6
  Top Layer w8: R164.1@1596.5,5785 1647.5,5734 1806,5734 ; C98.1@1761.5,5690 1807,5690 ; C99.1@1848.5,5690 1807,5690 ; U3.7@2124.61,5729.53 2005.47,5729.53 1965,5770 C94.2@1911.5,5770 1911.5,5740.5 1905,5734 1806,5734 ; 1806,5734 1806,5691 1807,5690
3-VC4: C91.2 C93.1 C94.1 R159.1 U3.5 | length 1117.6
  Top Layer w8: R159.1@1600,6130 1650,6130 1655,6125 1655,6095 1595,6035 1595,5945 1630,5910 1630,5830 1650,5810 1805,5810 ; C93.1@1765,5770 1805,5770 ; C94.1@1845,5770 1805,5770 ; C91.2@1911.5,5850 1971,5850 2052.1,5768.9 U3.5@2124.61,5768.9 ; 1950,5850 1950,5825 1935,5810 1805,5810 ; 1805,5770 1805,5810
3-VC5: C87.2 C90.1 C91.1 R155.1 U3.3 | length 1430.3
  Top Layer w8: R155.1@1600,6485 1665,6485 1690,6460 1690,6100 1620,6030 1620,5950 1680,5890 1805,5890 ; 1805,5850 1805,5890 ; C87.2@1915,5930 1945,5930 ; U3.3@2124.61,5808.27 2068.73,5808.27 2010,5867 2010,5901 1981,5930 1945,5930 ; 1805,5890 1935,5890 1945,5900 1945,5930
  Top Layer w10: C90.1@1761.5,5850 C91.1@1848.5,5850
3-VC6: C86.1 C87.1 R151.1 U3.1 | length 1269.3
  Top Layer w10: 2081,5877 2081,5856 2089,5848 2124.24,5848 U3.1@2124.61,5847.64
  Top Layer w12: R151.1@1756.5,6605 1794,6605 1806,6593 1806,6556 1760,6510 1760,6110 1805,6065 1805,5991 ; C86.1@1761.5,5930 1805,5930 ; C87.1@1848.5,5930 1805,5930 ; 2081,5877 2081,5938.22 2057.22,5962 1963,5962 1934,5991 1805,5991 ; 1805,5930 1805,5991
3.3_SW: C121.1 C122.1 C124.1 JP19.2 P6.1 R190.2 R191.2 R192.2 R195.2 R198.2 R199.2 R200.2 TP-19.1 U4.10 U4.16 U5.16 U6.1 U6.7 | length 1739.7
  Top Layer w12: U6.1@4164.4,1575.1 4229.9,1575.1 v1(4230,1575) 4270,1575 C121.1@4270,1565 ; U6.7@4164.4,1875.1 4234.9,1875.1 v1(4235,1875) ; R198.2@4510,1625 v1(4550,1625) ; R199.2@4510,1700 v1(4550,1700) ; R200.2@4510,1775 v1(4550,1775) ; R195.2@4550,1890 4550,1860 4565,1845 4580,1845 4590,1855 4590,1995 4605,2010 v1(4640,2010) ; C122.1@4625,1960 4640,1975 v1(4640,2010) ; U5.16@4638,2088.3 4638,2012 v1(4640,2010)
  Top Layer w24: U4.10@4314.6,2099.9 4385,2099.9 v1(4385,2101) ; U4.16@4314.6,2399.9 4314.6,2459.6 v1(4315,2460) 4315,2460.36 4335,2480.36 C124.1@4335,2525 ; C124.1@4331.5,2526 4369,2526 4389.5,2505.5 R190.2@4450,2505.5 ; R190.2@4450,2510 4450,2645 4480,2675 4545.55,2675 4547.47,2673.08 ; R192.2@4550,2506.5 4550,2670.55 4547.47,2673.08 ; R191.2@4650,2510 4650,2641.09 4582.74,2708.35 4547.47,2673.08
5V_USB: C125.1 JP19.3 P5.4 P5.6 R210.1 | length 2233.3
  Top Layer w24: JP19.3@4175,1225 4175,1100 4195,1080 v1(4360,1080) C125.1@4360,1125 ; v1(4600,585) 4600,535 4683.63,535 4698.63,550 4885,550 4925.04,590.04 4925.04,1225 ; P5.6@4850,1225 4925.04,1225 ; P5.4@4850,1325 4912,1325 4925.27,1311.73 4925.27,1225 4925.04,1225
  Bottom Layer w24: v1(4360,1080) 4565,875 4565,620 v1(4600,585)
AGND: C121.2 C122.2 C124.2 C125.2 C126.2 C127.2 C128.2 C129.2 C133.2 C134.2 C136.2 C137.1 P5.2 P5.10 P6.6 R204.1 R207.1 R208.1 R209.1 R215.1 TP-AGN.1 U4.9 U4.15 U5.3 U5.4 U5.5 U5.7 U5.8 U5.13 U5.14 U6.2 U6.8 U7.2 U7.3 U8.2 U8.5 | length 2312
  Top Layer w12: U6.2@4164.4,1625.1 4229.9,1625.1 v1(4230,1625) ; U6.8@4164.4,1925.1 4234.9,1925.1 v1(4235,1925) ; U7.2@4325,1255 4325,1215 4335,1205 v1(4360,1205) 4362,1207 U7.3@4362,1255 ; U5.8@4458.8,2307.3 4458.8,2365 v1@4471.9,2378.1 ; v1(4470,2380) v1@4471.9,2378.1 ; U5.7@4484.4,2307.3 4484.4,2365.6 v1@4471.9,2378.1 ; U5.5@4535.6,2307.3 4535.6,2380 4540,2384.4 4559.4,2384.4 v1(4560,2385) ; U5.13@4561.1,2088.3 4561.1,2151.1 v1(4570,2160) 4585,2145 4586.7,2145 U5.14@4586.7,2088.3 ; U5.4@4561.2,2307.3 4561.2,2383.8 v1(4560,2385) ; U5.3@4586.8,2307.3 4586.8,2378.2 4580,2385 v1(4560,2385)
  Top Layer w20: v1(4097,743) 4097,790.5 C136.2@4100,793.5 ; v1(4219,2526) C124.2@4268.5,2526 ; v1(4244,1122) 4291.5,1122 C125.2@4293.5,1124 ; C121.2@4336.5,1565 v1(4387,1565) ; C126.2@4360.43,1450 4361,1450.57 v1(4361,1501) ; R204.1@4450,1893.5 4454,1889.5 v1(4454,1842) ; C134.2@4456.5,450 v1(4501,450) ; C133.2@4456.5,525 v1(4504,525) ; v1(4474,1448) 4517.5,1448 R208.1@4519.5,1450 ; v1(4475,1373) 4516.5,1373 R207.1@4518.5,1375 ; v1(4475,1524) 4516.5,1524 R209.1@4518.5,1526 ; R215.1@4500,668.5 4501,667.5 v1(4501,623) ; C129.2@4500,1181.5 v1(4500,1232) ; C127.2@4600,318.5 4601,317.5 v1(4601,265) ; C128.2@4600,706.5 4602,708.5 v1(4602,752) ; C122.2@4625,1893.5 4627,1891.5 v1(4627,1839)
  Top Layer w24: v1(4189.05,974.87) 4189.05,975 U8.2@4255,975 ; v1@4213.57,118.35 v1(4213.57,117.59) 4165.41,117.59 4164.5,118.5 4164.5,179.6 4214.33,179.6 v1(4214.33,178.87) 4271.13,178.87 4300,150 TP-AGN.1@4425,150 ; U4.9@4314.6,2049.9 4386,2049.9 v1(4386,2049) ; U4.15@4314.6,2349.9 4389.9,2349.9 v1(4390,2350) ; U8.5@4444,875 4516.18,875 v1(4516.18,872.98)
ALERT: P6.3 U4.13 U5.11 | length 776.6
  Top Layer w12: U4.13@4314.6,2249.9 4314.7,2250 v1@4383.75,2250 ; v1(4385.79,2247.96) v1@4383.75,2250 ; U5.11@4509.9,2088.3 4509.9,2185 4489.9,2205 4430,2205 4385,2250 v1@4383.75,2250
  Bottom Layer w12: v1(4385.79,2247.96) 4580.43,2247.96 4678.38,2150 P6.3@4800,2150
CONV: P6.5 R204.2 U4.11 U5.9 | length 1600.3
  Top Layer w12: U4.11@4314.6,2149.9 4395,2149.9 4414.9,2130 4414.9,2030 4415,2029.9 4415,2025 v1(4418,2024) ; R204.2@4450,1960 4415,1995 4415,2024 v1(4418,2024) ; U5.9@4458.7,2088.3 4458.7,2035 4448.7,2025 4418,2025 v1(4418,2024)
  Bottom Layer w12: v1(4418,2024) 4571,1871 4835,1871 4870,1906 4870,2414 4800,2484 P6.5@4800,2550
CS: P5.9 P6.9 R198.1 R207.2 U6.3 | length 3740
  Top Layer w12: U6.3@4164.4,1675.1 4164.5,1675 4325,1675 4375,1625 4440,1625 4440,1590 4425,1575 4425,1430 4440,1415 4545,1415 4585,1375 4585,1110 4670,1025 P5.9@4750,1025
  Bottom Layer w12: P5.9@4750,1025 4796.5,978.5 4869.26,978.5 4936.5,1045.74 4936.5,3213.5 P6.9@4800,3350
DRDY: P6.4 U4.12 U5.10 | length 822
  Top Layer w12: U4.12@4314.6,2199.9 4314.7,2200 4390,2200 v1@4405.9,2184.1 ; v1(4405.9,2183.59) v1@4405.9,2184.1 ; U5.10@4484.3,2088.3 4484.3,2145 4464.3,2165 4425,2165 v1@4405.9,2184.1
  Bottom Layer w12: v1(4405.9,2183.59) 4359.79,2229.7 4359.79,2258.72 4375.02,2273.96 4534.41,2273.96 4610.45,2350 P6.4@4800,2350
FAULT: P6.2 U4.14 U5.12 | length 1209.3
  Top Layer w12: U4.14@4314.6,2299.9 4314.6,2299.96 v1(4394.09,2299.96) 4454.05,2240 4514.9,2240 4534.9,2220 4534.9,2088.9 U5.12@4535.5,2088.3
  Bottom Layer w12: v1(4394.09,2299.96) 4332,2299.96 4310,2277.96 4310,2099 4334,2075 4675,2075 P6.2@4800,1950
GPIO0/I2C(SDA): P5.3 R192.1 U5.2 | length 1201.3
  Top Layer w12: R192.1@4550,2443.5 4612.4,2381.1 4612.4,2307.3 4612.4,2187.86 4690,2110.26 4690,1385 P5.3@4750,1325
GPIO1/I2C(SCL): P5.1 R191.1 U5.1 | length 1069.9
  Top Layer w12: R191.1@4650,2443.5 4650,2380 4638,2368 4638,2307.3 4638,2205.04 4710.5,2132.54 4710.5,1685 4750,1645.5 P5.1@4750,1425
NetC22_2: C22.2 R84.1 R89.2 TP-2.1 U1.20 | length 1021.2
  Top Layer w8: TP-2.1@1910,710 1942,710 1992,660 2025,660 2061,624 2248.48,624 2280.7,656.22 2280.7,806.2 ; TP-2.1@1955,711 TP-2.1@1959,711 ; C22.2@2235,760 2235,792.92 2248.28,806.2 2280.7,806.2 ; U1.20@2261.42,1054.61 2261.42,986.58 2319,929 2319,891.5 R89.2@2276,848.5 ; R89.2@2280.7,845 2280.7,806.2 ; R84.1@2316.29,760 2316.29,797.72 2307.81,806.2 2280.7,806.2
NetC23_2: C23.2 R85.1 R91.2 TP-4.1 U1.61 | length 866.2
  Top Layer w8: TP-4.1@2100,2020 2197,2020 2255,1962 2255,1774 ; R85.1@2210,1818.5 2210,1785.06 2221.06,1774 2255,1774 ; 2233.4,1773.94 2233.4,1754.6 2223.25,1744.46 2223.25,1604.21 2261.42,1566.05 U1.61@2261.42,1505.39 ; R91.2@2260,1721.5 2255,1726.5 2255,1774 ; C23.2@2290,1818.5 2290,1785 2279,1774 2255,1774
NetC31_1: C31.1 C33.2 R106.1 R108.1 U1.47 | length 715.6
  Top Layer w8: U1.47@2575.39,1407.95 2609.95,1407.95 2705,1503 ; C33.2@2705,1528.5 2705,1503 ; C31.1@2783.5,1480 2745,1480 ; R108.1@2783.5,1555 2754,1555 2745,1546 2745,1516 ; R106.1@3015,1643.5 3015,1640 2891,1516 2745,1516 ; 2705,1503 2728,1480 2745,1480 ; 2745,1480 2745,1516
NetC32_1: C32.1 C33.1 R99.1 R101.1 U1.48 | length 777.2
  Top Layer w8: U1.48@2575.39,1427.64 2606.04,1427.64 2663.85,1485.45 2663.85,1581.85 2677,1595 2705,1595 2705,1672.9 2737.1,1705 2746.06,1705 ; 2749.31,1630 R101.1@2780,1630 ; C32.1@2780,1705 2746.06,1705 ; R99.1@2940,1640 2891.56,1591.56 2752.05,1591.56 2744.89,1598.72 2744.89,1703.83 2746.06,1705
NetC39_1: C39.1 U1.16 | length 291.8
  Top Layer w8: 2066,1117 2081.36,1132.36 U1.16@2124.61,1132.36
  Top Layer w12: C39.1@2005,915.43 2005,1056 2066,1117
NetC58_2: C58.2 R127.1 R132.2 TP-8.1 U2.20 | length 901.7
  Top Layer w8: TP-8.1@2070,2765 2078,2757 2252,2757 2282.66,2787.66 2282.66,2935.17 ; R127.1@2240,2895 2240,2922.05 2253.12,2935.17 2282.66,2935.17 ; U2.20@2261.42,3221.65 2261.42,3158.06 2332.16,3087.32 2332.16,2954.33 2309.8,2931.98 ; R132.2@2280,2985 2282.66,2985 2282.66,2935.17 ; C58.2@2320,2895 2320,2921.78 2309.8,2931.98 ; 2282.66,2935.17 2306.61,2935.17 2309.8,2931.98
NetC59_2: C59.2 R128.1 R134.2 TP-10.1 U2.61 | length 914.4
  Top Layer w8: TP-10.1@2040,4260 2090,4210 2090,4196.07 2130.1,4155.97 2193,4155.97 2244,4104.97 2244,3950 2260,3950 ; C59.2@2210,3995 2210,3960 2220,3950 ; 2240,3950 2220,3950 ; R134.2@2260,3905 2260,3950 ; U2.61@2261.42,3678.35 2261.42,3723.63 2225,3760.05 2225,3945 2220,3950 ; R128.1@2285,3995 2285,3960 2275,3950 2260,3950
NetC70_1: C70.1 C72.2 R144.1 R146.1 U2.47 | length 849.8
  Top Layer w8: U2.47@2578.35,3577.95 2606.76,3577.95 2608.81,3580 2660,3580 2720,3640 ; C72.2@2720,3685 2720,3640 ; C70.1@2795,3640 2760,3640 ; R146.1@2795,3715 2765,3715 2760,3710 2760,3680 ; R144.1@3110,3800 3110,3705 3085,3680 2760,3680 ; 2720,3640 2760,3640 ; 2760,3640 2760,3680
NetC71_1: C71.1 C72.1 R140.1 R141.1 U2.48 | length 851.5
  Top Layer w8: U2.48@2578.35,3597.64 2612.64,3597.64 2635,3620 2635,3725 2700,3790 2720,3790 ; C72.1@2720,3755 2720,3790 ; C71.1@2795,3790 2755,3790 ; R141.1@2795,3865 2765,3865 2755,3855 2755,3790 ; R140.1@3035,3800 3035,3775 3010,3750 2765,3750 2755,3760 2755,3790 ; 2720,3790 2755,3790
NetC77_1: C77.1 U2.16 | length 290
  Top Layer w8: 2069,3292 2079.36,3302.36 U2.16@2124.61,3302.36
  Top Layer w16: C77.1@2000,3090.43 2000,3223 2069,3292
NetC96_2: C96.2 R165.1 R169.2 TP-14.1 U3.20 | length 1025.3
  Top Layer w8: TP-14.1@1975,4925 2040,4925 2055,4940 2055,4975 2085,5005 2220,5005 2245,5030 2245,5220 ; R165.1@2210,5165 2210,5205 2225,5220 2245,5220 ; R169.2@2260,5270 2260,5220 ; U3.20@2261.42,5471.65 2261.42,5393.58 2300,5355 2300,5240 2280,5220 ; C96.2@2290,5165 2290,5210 2280,5220 ; 2245,5220 2260,5220 ; 2260,5220 2280,5220
NetC97_2: C97.2 R166.1 R170.2 TP-16.1 U3.61 | length 834.5
  Top Layer w8: TP-16.1@2100,6355 2160,6355 2175,6370 2250,6370 2265,6355 2265,6175 ; C97.2@2220,6228.5 2220,6190 2235,6175 ; U3.61@2261.42,5928.35 2261.42,5975 2226.42,6010 2226.42,6166.42 2235,6175 ; R170.2@2265,6135 2265,6175 ; R166.1@2300,6228.5 2300,6185 2290,6175 2265,6175 ; 2235,6175 2265,6175
NetC104_1: C104.1 C106.2 R184.1 R185.1 U3.47 | length 896.3
  Top Layer w8: U3.47@2578.35,5827.95 2615,5827.95 2677.05,5890 2710,5890 ; C106.2@2710,5945 2710,5890 ; C104.1@2795,5890 2755,5890 ; R185.1@2795,5970 2765,5970 2755,5960 2755,5925 ; R184.1@3135,6065 3135,5985 3075,5925 2755,5925 ; 2710,5890 2755,5890 ; 2755,5890 2755,5925
NetC105_1: C105.1 C106.1 R179.1 R181.1 U3.48 | length 915.7
  Top Layer w8: U3.48@2578.35,5847.64 2612,5847.64 2635,5870.64 2635,6015 2670,6050 2710,6050 ; C106.1@2710,6015 2710,6050 ; R181.1@2795,6050 2745,6050 ; C105.1@2795,6130 2755,6130 2745,6120 2745,6050 ; R179.1@3045,6065 3045,6025 3030,6010 2770,6010 2745,6035 2745,6050 ; 2710,6050 2745,6050
NetC112_1: C112.1 U3.16 | length 303.9
  Top Layer w8: 2055,5525 2055,5529 2078.36,5552.36 U3.16@2124.61,5552.36
  Top Layer w15: C112.1@1980,5335.43 1980,5410 2025,5455 2025,5480 2055,5510 2055,5525
NetC120_1: C120.1 C123.1 C135.1 D4.1 D4.2 D4.5 D4.6 D4.8 R212.1 TP-20.1 U4.1 U4.7 U6.10 U6.16 U9.5 | length 1223.3
  Top Layer w12: 3570,1175 R212.1@3615,1175 ; v1(3715,1875) 3715.1,1875.1 U6.10@3785.4,1875.1 ; v1(3765,2345) 3796,2345 3810.43,2359.43 C135.1@3810.43,2400 v1(3860,2400) 3860.1,2399.9 U4.1@3935.6,2399.9 ; v1(3865,2100) 3865.1,2099.9 U4.7@3935.6,2099.9
  Top Layer w15: v1(3570,1245) 3570,1175 3570,1149 3613,1106 U9.5@3613,1092
  Top Layer w20: C123.1@3681.5,1575 v1(3722,1575) ; TP-20.1@3725,1380 3722,1383 v1(3722,1575) ; U6.16@3787.99,1575 v1(3722,1575)
  Bottom Layer w12: v1(3520,2100) v1(3765,2345)
NetC126_1: C126.1 JP19.1 U7.5 | length 238.7
  Top Layer w20: JP19.1@4177,1425 4231,1425 ; U7.5@4287.6,1354.13 4250.87,1354.13 4231,1374 4231,1425 ; C126.1@4289.57,1450 4264.57,1425 4231,1425
NetC127_1: C127.1 C128.1 C129.1 C133.1 C134.1 R210.2 R211.1 T1.2 TP-SW1.1 U7.1 U8.8 | length 2382.8
  Top Layer w24: R211.1@4100,1035 4100,1238.28 4136.72,1275 4226.39,1275 4246.39,1255 4288,1255 4288,1215.23 4332.67,1170.56 4416.51,1170.56 4432.5,1154.57 4432.5,1115 4500,1115 4500,1025 ; C133.1@4390,525 4390,450 4437.78,402.22 4519.8,402.22 4537.02,385 4600,385 4600,465 4564,465 4545,484 4545,585 4600,640 4675,640 ; U8.8@4444,1025 4500,1025 ; TP-SW1.1@4825,640 4675,640 ; 4500,1025 4675,850 4675,640
  Top Layer w30: T1.2@4221.6,501 4277,501 4328,450 C134.1@4390,450
NetC130_1: C130.1 L1.2 U9.1 | length 277.3
  Top Layer w20: L1.2@3525,865 3532,865 3574.5,907.5 ; C130.1@3526,993.5 3526,956 3574.5,907.5 ; U9.1@3612.6,995.87 3612.6,945.6 3574.5,907.5
NetC131_1: C131.1 C132.1 L1.1 T1.5 | length 895.5
  Top Layer w24: L1.1@3525,780 3525,725 3535,715 3650,715 ; C132.1@3650,765 3650,715 ; C131.1@3750,765 3750,715 ; T1.5@3896.4,501 3966,501 3995,530 3995,665 3945,715 3750,715 ; 3650,715 3750,715
NetC136_1: C136.1 R211.2 U8.4 | length 274.7
  Top Layer w10: R211.2@4100,968.5 C136.1@4100,856.5 4158.5,856.5 4177,875 U8.4@4255,875
NetD1_1: D1.1 R77.1 | length 116
  Top Layer w8: R77.1@2916.5,680 D1.1@3032.52,680
NetD1_2: D1.2 Q5.1 Q5.2 Q5.5 Q5.6 Q5.8
NetD2_1: D2.1 R123.1 | length 106
  Top Layer w8: R123.1@2916.5,2840 D2.1@3022.52,2840
NetD2_2: D2.2 Q12.1 Q12.2 Q12.5 Q12.6 Q12.8
NetD3_1: D3.1 R161.1 | length 106
  Top Layer w8: R161.1@2916.5,5120 D3.1@3022.52,5120
NetD3_2: D3.2 Q20.1 Q20.2 Q20.5 Q20.6 Q20.8 | length 320.4
  Top Layer w8: Q20.8@3077.8,5240 3175,5240 3190,5225 3190,5130 3180,5120 3087.3,5120 D3.2@3087.2,5120.1
NetD4_3: D4.3 R196.2 | length 88.1
  Top Layer w8: R196.2@3585,2000 3585,2036.16 3600.59,2051.75 D4.3@3600.59,2081.69
NetD4_4: D4.4 D4.7 R193.1 R202.2
NetD5_1: D5.1 T1.6 | length 172.1
  Top Layer w10: D5.1@3747.5,345 3803.5,401 T1.6@3896.4,401
NetD6_1: D6.1 T1.4 | length 170
  Top Layer w10: D6.1@3747.5,550 3798.5,601 T1.4@3896.4,601
NetJ1_2: J1.2 R68.1 TP-C2.1 | length 1836.2
  Top Layer w12: TP-C2.1@1825,2180 1930,2075 R68.1@1930,1825
  Top Layer w25: J1.2@555,1935 880,2260 1695,2260 1775,2180 TP-C2.1@1825,2180
NetJ2_1: J2.1 R84.2 RT1.1 | length 4917.6
  Top Layer w8: R84.2@2315,693.5 2317,691.5 v1(2317,651) ; J2.1@4447,4359 4487,4319 4533,4319 4550,4336 RT1.1@4550,4388.5
  Bottom Layer w8: v1@2314.4,653.42 2483.42,653.42 2806,976 2806,1783.19 4450,3427.19 J2.1@4450,4365
NetJ3_1: J3.1 R85.2 RT2.1 | length 3973.7
  Top Layer w8: RT2.1@4200,4388.5 4200,4340 4223,4317 4256,4317 J3.1@4298,4359
  Top Layer w10: R85.2@2210,1881.5 v1(2210.03,1926.43)
  Top Layer w24: R85.2@2209,1878 R85.2@2210.03,1878
  Bottom Layer w8: v1@2209.8,1923.12 2233.8,1947.12 2328.52,1947.12 2379.64,1896 2872.79,1896 4300,3323.21 J3.1@4300,4365
NetJ4_2: J4.2 R115.1 TP-C4.1 | length 2044.2
  Top Layer w24: J4.2@561,4080 561,4081 704.92,4224.92 704.92,4381.59 849.79,4526.46 1693.54,4526.46 1785,4435 1785,4230 1910,4105 1910,4010 R115.1@1930,3990
NetJ5_1: J5.1 R127.2 RT3.1 | length 4083.1
  Top Layer w8: v1(2240.03,2786.19) R127.2@2240.03,2829.53 ; J5.1@4425,5271 4468,5228 4536,5228 4550,5242 RT3.1@4550,5298.5
  Bottom Layer w8: v1@2239.33,2786.74 2239.33,2755.49 2250.96,2743.86 2356.24,2743.86 2397.59,2785.2 2397.59,3082.03 2454.49,3138.94 2760,3138.94 2975.75,3355 2975.75,3871.15 2989.72,3885.12 3192.48,3885.12 4425,5117.64 J5.1@4425,5271
NetJ6_1: J6.1 R128.2 RT4.1 | length 3069.4
  Top Layer w8: RT4.1@4175,5298.5 4175,5252 4198,5229 4257,5229 J6.1@4300,5272
  Top Layer w24: R128.2@2285,4064 v1(2285.03,4099.43)
  Bottom Layer w8: v1@2285.19,4102.12 2285.19,4018.66 2372.76,3931.09 3193.2,3931.09 4300,5037.89 J6.1@4300,5272 J6.1@4300,5280
NetJ7_2: J7.2 R152.1 TP-C6.1 | length 2785.8
  Top Layer w10: TP-C6.1@1785,6755 TP-C6.1@1790,6755 1815,6755 1845,6725 v3(1845,6670) ; v1(1890,6285) 1890,6267 R152.1@1927,6230
  Top Layer w24: J7.2@560,5855 695,5990 695,6801 774,6880 1640,6880 1762,6758 1782,6758 TP-C6.1@1785,6755 ; R152.1@1927,6230 R152.1@1927,6238
  Bottom Layer w10: v3(1845,6670) 1890,6625 v1(1890,6285)
NetJ8_1: J8.1 R165.2 RT5.1 | length 3398.9
  Top Layer w8: R165.2@2209,5098.5 2210,5097.5 v1(2210,5055) ; J8.1@4426,6208 4472,6162 4511,6162 4525,6176 RT5.1@4525,6218.5
  Bottom Layer w8: v1@2210,5050 2245,5015 2300,5015 2315,5030 2315,5345 2360,5390 2725,5390 2930,5595 2930,5675 2975,5720 2975,6005 2990,6020 4350,6020 4425,6095 4425,6207 J8.1@4426,6208
NetJ9_1: J9.1 R166.2 RT6.1 | length 2469.2
  Top Layer w8: R166.2@2300,6291.5 2301,6292.5 v1(2301,6340) ; RT6.1@4200,6218.5 4200,6185 4222,6163 4251,6163 J9.1@4297,6209
  Bottom Layer w8: v1(2301,6340) 2390,6251 2899,6251 2970,6180 2970,6100 2995,6075 4250,6075 4300,6125 4300,6206 J9.1@4297,6209
NetJP1_2: JP1.2 R13.1 | length 144.8
  Top Layer w24: JP1.2@556,5598 698,5598 R13.1@700,5600
NetJP2_2: JP2.2 R14.1 | length 144.8
  Top Layer w24: JP2.2@556,5448 698,5448 R14.1@700,5450
NetJP3_2: JP3.2 R15.1 | length 144.8
  Top Layer w24: JP3.2@556,5298 698,5298 R15.1@700,5300
NetJP4_2: JP4.2 R16.1 | length 144.8
  Top Layer w24: JP4.2@556,5148 698,5148 R16.1@700,5150
NetJP5_2: JP5.2 R17.1 | length 144.8
  Top Layer w24: JP5.2@556,4998 698,4998 R17.1@700,5000
NetJP6_2: JP6.2 R18.1 | length 144.8
  Top Layer w24: JP6.2@556,4848 558,4850 R18.1@700,4850
NetJP7_2: JP7.2 R30.1 | length 144.4
  Top Layer w24: JP7.2@556,3854 635,3854 636,3855 R30.1@700,3855
NetJP8_2: JP8.2 R31.1 | length 144.4
  Top Layer w24: JP8.2@556,3704 635,3704 636,3705 R31.1@700,3705
NetJP9_2: JP9.2 R32.1 | length 144.4
  Top Layer w24: JP9.2@556,3554 635,3554 636,3555 R32.1@700,3555
NetJP10_2: JP10.2 R33.1 | length 144.4
  Top Layer w24: JP10.2@556,3404 635,3404 636,3405 R33.1@700,3405
NetJP11_2: JP11.2 R34.1 | length 144.4
  Top Layer w24: JP11.2@556,3254 635,3254 636,3255 R34.1@700,3255
NetJP12_2: JP12.2 R35.1 | length 144.4
  Top Layer w24: JP12.2@556,3104 635,3104 636,3105 R35.1@700,3105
